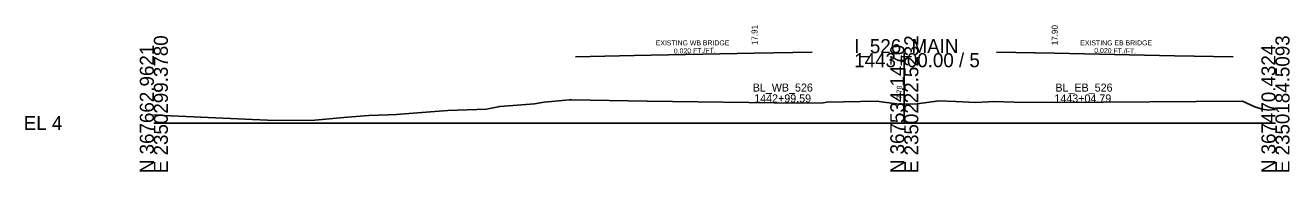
# Model space of a CAD drawing. Extents: x -170 to 2527928, y -10 to 1619750.
# Drawn here: x 4974.3 to 5227, y 5490.3 to 5519.5 of the extents above; entities that cross this region are included whole.
import ezdxf

# ---------------------------------------------------------------- set-up
doc = ezdxf.new("R2010")
doc.units = 0
for name, color, linetype in [('RD_GPK_XS_Cell', 7, 'Continuous'), ('RD_XS_Bridge', 7, 'Continuous'), ('RD_XS_ExGround', 7, 'Continuous'), ('RD_XS_TX_Elev_EX', 7, 'Continuous'), ('RD_XS_TX_Slope', 7, 'Continuous'), ('RD_XS_TX_Station', 7, 'Continuous')]:
    doc.layers.add(name, color=color, linetype=linetype)

msp = doc.modelspace()

# ---------------------------------------------------------------- linework, layer by layer
at = {"layer": 'RD_GPK_XS_Cell'}
for p, q in [((5150, 5500), (5150, 5513.93)), ((5000, 5500), (5150, 5500)), ((5150, 5500), (5224.19, 5500))]:
    msp.add_line(p, q, dxfattribs=at)
at = {"layer": 'RD_XS_Bridge'}
for p, q in [((5084.25, 5513.2), (5096, 5513.43)), ((5096, 5513.43), (5120, 5513.91)), ((5120, 5513.91), (5131.6, 5514.14)), ((5168.4, 5514.13), (5180, 5513.9)), ((5176, 5513.98), (5180, 5513.9)), ((5180, 5513.9), (5204, 5513.42)), ((5204, 5513.42), (5215.75, 5513.19))]:
    msp.add_line(p, q, dxfattribs=at)
at = {"layer": 'RD_XS_ExGround'}
msp.add_lwpolyline([(5000, 5501.6), (5002.01, 5501.47), (5018.27, 5500.78), (5024.19, 5500.52), (5032.18, 5500.55), (5038.69, 5501.15), (5042.99, 5501.5), (5046.84, 5501.64), (5048.51, 5501.67), (5050.08, 5501.86), (5058.74, 5502.51), (5066.51, 5502.79), (5069.13, 5503.3), (5076.09, 5503.85), (5078.04, 5504.19), (5083.08, 5504.62), (5083.31, 5504.64), (5083.33, 5504.64), (5083.48, 5504.64), (5098.61, 5504.39), (5129.07, 5503.96), (5133.77, 5504.04), (5134.5, 5504.15), (5144.56, 5504.34), (5145.4, 5504.25), (5149.01, 5503.76), (5150, 5503.78), (5152.54, 5503.82), (5156.9, 5504.44), (5160.27, 5504.29), (5164.24, 5504.12), (5166.8, 5504.22), (5167.88, 5504.32), (5171.95, 5504.13), (5180.51, 5504.11), (5217.59, 5504.36), (5220.03, 5503.21), (5221.51, 5502.77), (5222.78, 5502.55), (5224.19, 5502.68)], dxfattribs=at)

# ---------------------------------------------------------------- texts
at = {"layer": 'RD_GPK_XS_Cell'}
for s, p in [('E 2350299.3780', (5002.8, 5490)), ('E 2350222.5232', (5152.8, 5490)), ('E 2350184.5093', (5226.99, 5490)), ('N 367662.9621', (5000, 5490)), ('N 367534.1470', (5150, 5490)), ('N 367470.4324', (5224.19, 5490))]:
    msp.add_text(s, height=2.8, rotation=90, dxfattribs=at).set_placement(p)
for s, p in [('I_526_MAIN', (5140, 5513.93)), ('1443+00.00 / 5', (5140, 5511.13)), ('EL 4', (4974, 5498.6))]:
    msp.add_text(s, height=2.8, dxfattribs=at).set_placement(p)
at = {"layer": 'RD_XS_Bridge'}
for s, p in [('EXISTING WB BRIDGE', (5100.31, 5515.48)), ('EXISTING EB BRIDGE', (5185.17, 5515.48))]:
    msp.add_text(s, height=1, dxfattribs=at).set_placement(p)
at = {"layer": 'RD_XS_TX_Elev_EX'}
msp.add_text('7.78', height=1, rotation=90, dxfattribs=at).set_placement((5149.5, 5504.78))
at = {"layer": 'RD_XS_TX_Slope'}
for rotation, p in [(1.1458, (5103.94, 5513.84)), (358.8542, (5187.95, 5513.99))]:
    msp.add_text('0.020 FT./FT.', height=1, rotation=rotation, dxfattribs=at).set_placement(p)
at = {"layer": 'RD_XS_TX_Station'}
for s, p in [(' 17.91', (5120.66, 5515.09)), (' 17.90', (5180.66, 5515.07))]:
    msp.add_text(s, height=1.2, rotation=90, dxfattribs=at).set_placement(p)
for s, p in [('BL_WB_526', (5119.71, 5506.27)), ('BL_EB_526', (5180.2, 5506.26)), ('1442+99.59', (5120, 5504.11)), ('1443+04.79', (5180, 5504.1))]:
    msp.add_text(s, height=1.6, dxfattribs=at).set_placement(p)

doc.saveas('drawing.dxf')
